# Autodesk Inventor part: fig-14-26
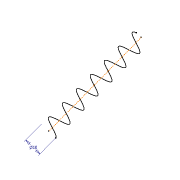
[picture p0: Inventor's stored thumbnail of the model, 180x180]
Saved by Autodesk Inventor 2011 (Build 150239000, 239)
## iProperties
Created: 2007-03
Part Number: fig-14-26
Document SubType Name: Modeling
Designer: Administrator
Density: 1 g/cm^3
Author: Administrator
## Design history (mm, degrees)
node "Sketch1"
sketch "3D Sketch1"
  node "Helical Curve2" dims "d4" = 10, "d5" = 66.31, "d6" = 10, "d7" = 0
